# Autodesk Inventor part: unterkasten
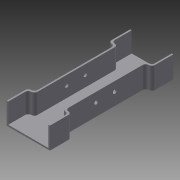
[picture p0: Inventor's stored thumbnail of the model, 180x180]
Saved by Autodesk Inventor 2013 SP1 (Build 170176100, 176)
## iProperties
Created: 2012-11
Part Number: unterkasten
Material: Allgemein
Document SubType Name: Modeling
Designer: macuser
Density: 1 g/cm^3
Author: macuser
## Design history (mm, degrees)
sketch "Skizze1"
  geometry: L1 (0, -56)-(0, 56) reference; L2 (-364, 0)-(364, 0) reference; L3 (-260, 40)-(260, 40); L4 (260, 40)-(260, -40); L5 (260, -40)-(-260, -40); L6 (-260, -40)-(-260, 40); 1 further point
  constraints: 8 end point, 2 parallel, 1 horizontal, 1 perpendicular, 2 other
  dimensions: "d0" = 520 distance of L4.end L5.end; "d1" = 80 distance of L3.end L4.end
extrude "Extrusion1" new body sketch "Skizze1" distance "d2" = 100; taper "d3" = 0 deg
feature "Wandstärke1" dims "d4" = 5
sketch "Skizze2"
  geometry: L1 (-40, 260)-(-40, -260) reference; L2 (-40, -260)-(40, -260) reference; L3 (40, 260)-(-40, 260) reference; L4 (0, -260)-(0, 260); L5 (0, 0)-(0, -30); L6 (0, -30)-(-40, -30); L7 (0, 0)-(0, 30); L8 (0, 30)-(-40, 30)
  constraints: 10 end point, 4 point on line, 2 midpoint, 2 perpendicular
  dimensions: "d5" = 30 distance of L5.start L5.end; "d6" = 30 distance of L5.start L7.end
hole "Bohrung1" sketch "Skizze2" at (0, -30), (0, 30) diameter "d7" = 12; stored, may be unused: countersink angle "d11" = 90 deg, drill point angle "d13" = 118 deg; dims "d8" = 6, "d9" = 4, "d10" = 2, "d12" = 8
sketch "Skizze3"
  geometry: L1 (-40, 260)-(-40, -260) reference; L2 (-40, -260)-(40, -260) reference; L3 (40, 260)-(-40, 260) reference; L4 (0, -364)-(0, 364) reference; L5 (56, 0)-(-56, 0) reference; L6 (-40, 260)-(-40, -260); L7 (0, 260)-(0, -260); L8 (-30, 260)-(-30, -260); 1 further point
  constraints: 6 end point, 4 point on line, 2 midpoint, 1 collinear, 1 perpendicular
  dimensions: "d14" = 10 distance between parallel lines of L6 L8
extrude "Extrusion2" cut sketch "Skizze3" distance "d15" = 100; taper "d16" = 0 deg
sketch "Skizze4"
  geometry: L1 (40, -260)-(40, 260) reference; L2 (-30, 260)-(40, 260); L3 (40, 260)-(40, 190); L4 (40, 190)-(-30, 190); L5 (-30, 190)-(-30, 260); L6 (-30, -260)-(40, -260); L7 (40, -260)-(40, -190); L8 (40, -190)-(-30, -190); L9 (-30, -190)-(-30, -260); 1 further point
  constraints: 16 end point, 4 parallel, 2 horizontal, 2 perpendicular, 1 point on line
  dimensions: "d17" = 70 distance of L2.end L3.end; "d18" = 70 distance of L8.end L7.end; "d19" = 70 distance of L7.end L6.end
extrude "Extrusion3" join sketch "Skizze4" distance "d20" = 20; taper "d21" = 0 deg
sketch "Skizze5"
  geometry: L1 (0, 0)-(0, 520) reference; L2 (65, 0)-(0, 0); L3 (0, 0)-(0, 65); L4 (0, 65)-(65, 65); L5 (65, 65)-(65, 0); L6 (65, 520)-(0, 520); L7 (0, 520)-(0, 455); L8 (0, 455)-(65, 455); L9 (65, 455)-(65, 520); 1 further point
  constraints: 16 end point, 4 parallel, 2 horizontal, 2 perpendicular, 2 point on line
  dimensions: "d22" = 65 distance of L2.end L3.end; "d23" = 65 distance of L7.end L6.end
extrude "Extrusion4" cut sketch "Skizze5" distance "d24" = 20; taper "d25" = 0 deg
sketch "Skizze6"
  geometry: L1 (30, -260)-(30, 260) reference; L2 (-40, 260)-(30, 260); L3 (30, 260)-(30, 190); L4 (30, 190)-(-40, 190); L5 (-40, 190)-(-40, 260); L6 (-40, -260)-(30, -260); L7 (30, -260)-(30, -190); L8 (30, -190)-(-40, -190); L9 (-40, -190)-(-40, -260); 1 further point
  constraints: 16 end point, 4 parallel, 2 horizontal, 2 perpendicular, 2 point on line
  dimensions: "d26" = 70 distance of L2.end L3.end; "d27" = 70 distance of L7.end L6.end
extrude "Extrusion5" join sketch "Skizze6" distance "d28" = 20; taper "d29" = 0 deg
sketch "Skizze7"
  geometry: L1 (0, 520)-(0, 0) reference; L2 (-65, 520)-(0, 520); L3 (0, 520)-(0, 455); L4 (0, 455)-(-65, 455); L5 (-65, 455)-(-65, 520); L6 (-65, 0)-(0, 0); L7 (0, 0)-(0, 65); L8 (0, 65)-(-65, 65); L9 (-65, 65)-(-65, 0); 1 further point
  constraints: 16 end point, 4 parallel, 2 horizontal, 2 perpendicular, 2 point on line
  dimensions: "d30" = 65 distance of L2.end L3.end; "d31" = 65 distance of L7.end L6.end
extrude "Extrusion6" cut sketch "Skizze7" distance "d32" = 20; taper "d33" = 0 deg
fillet "Rundung1" dims "d34" = 10
node "Volumenkörper1"
